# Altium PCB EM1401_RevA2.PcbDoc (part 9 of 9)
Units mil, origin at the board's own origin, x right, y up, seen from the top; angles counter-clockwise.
Board outline 7800 x 5300 mil, 6 copper layers (Top Layer, MidLayer1, MidLayer2, MidLayer3, MidLayer4, Bottom Layer), stack 16.8 mil thick; 751 components, 531 nets, 2554 pads, 1388 vias.
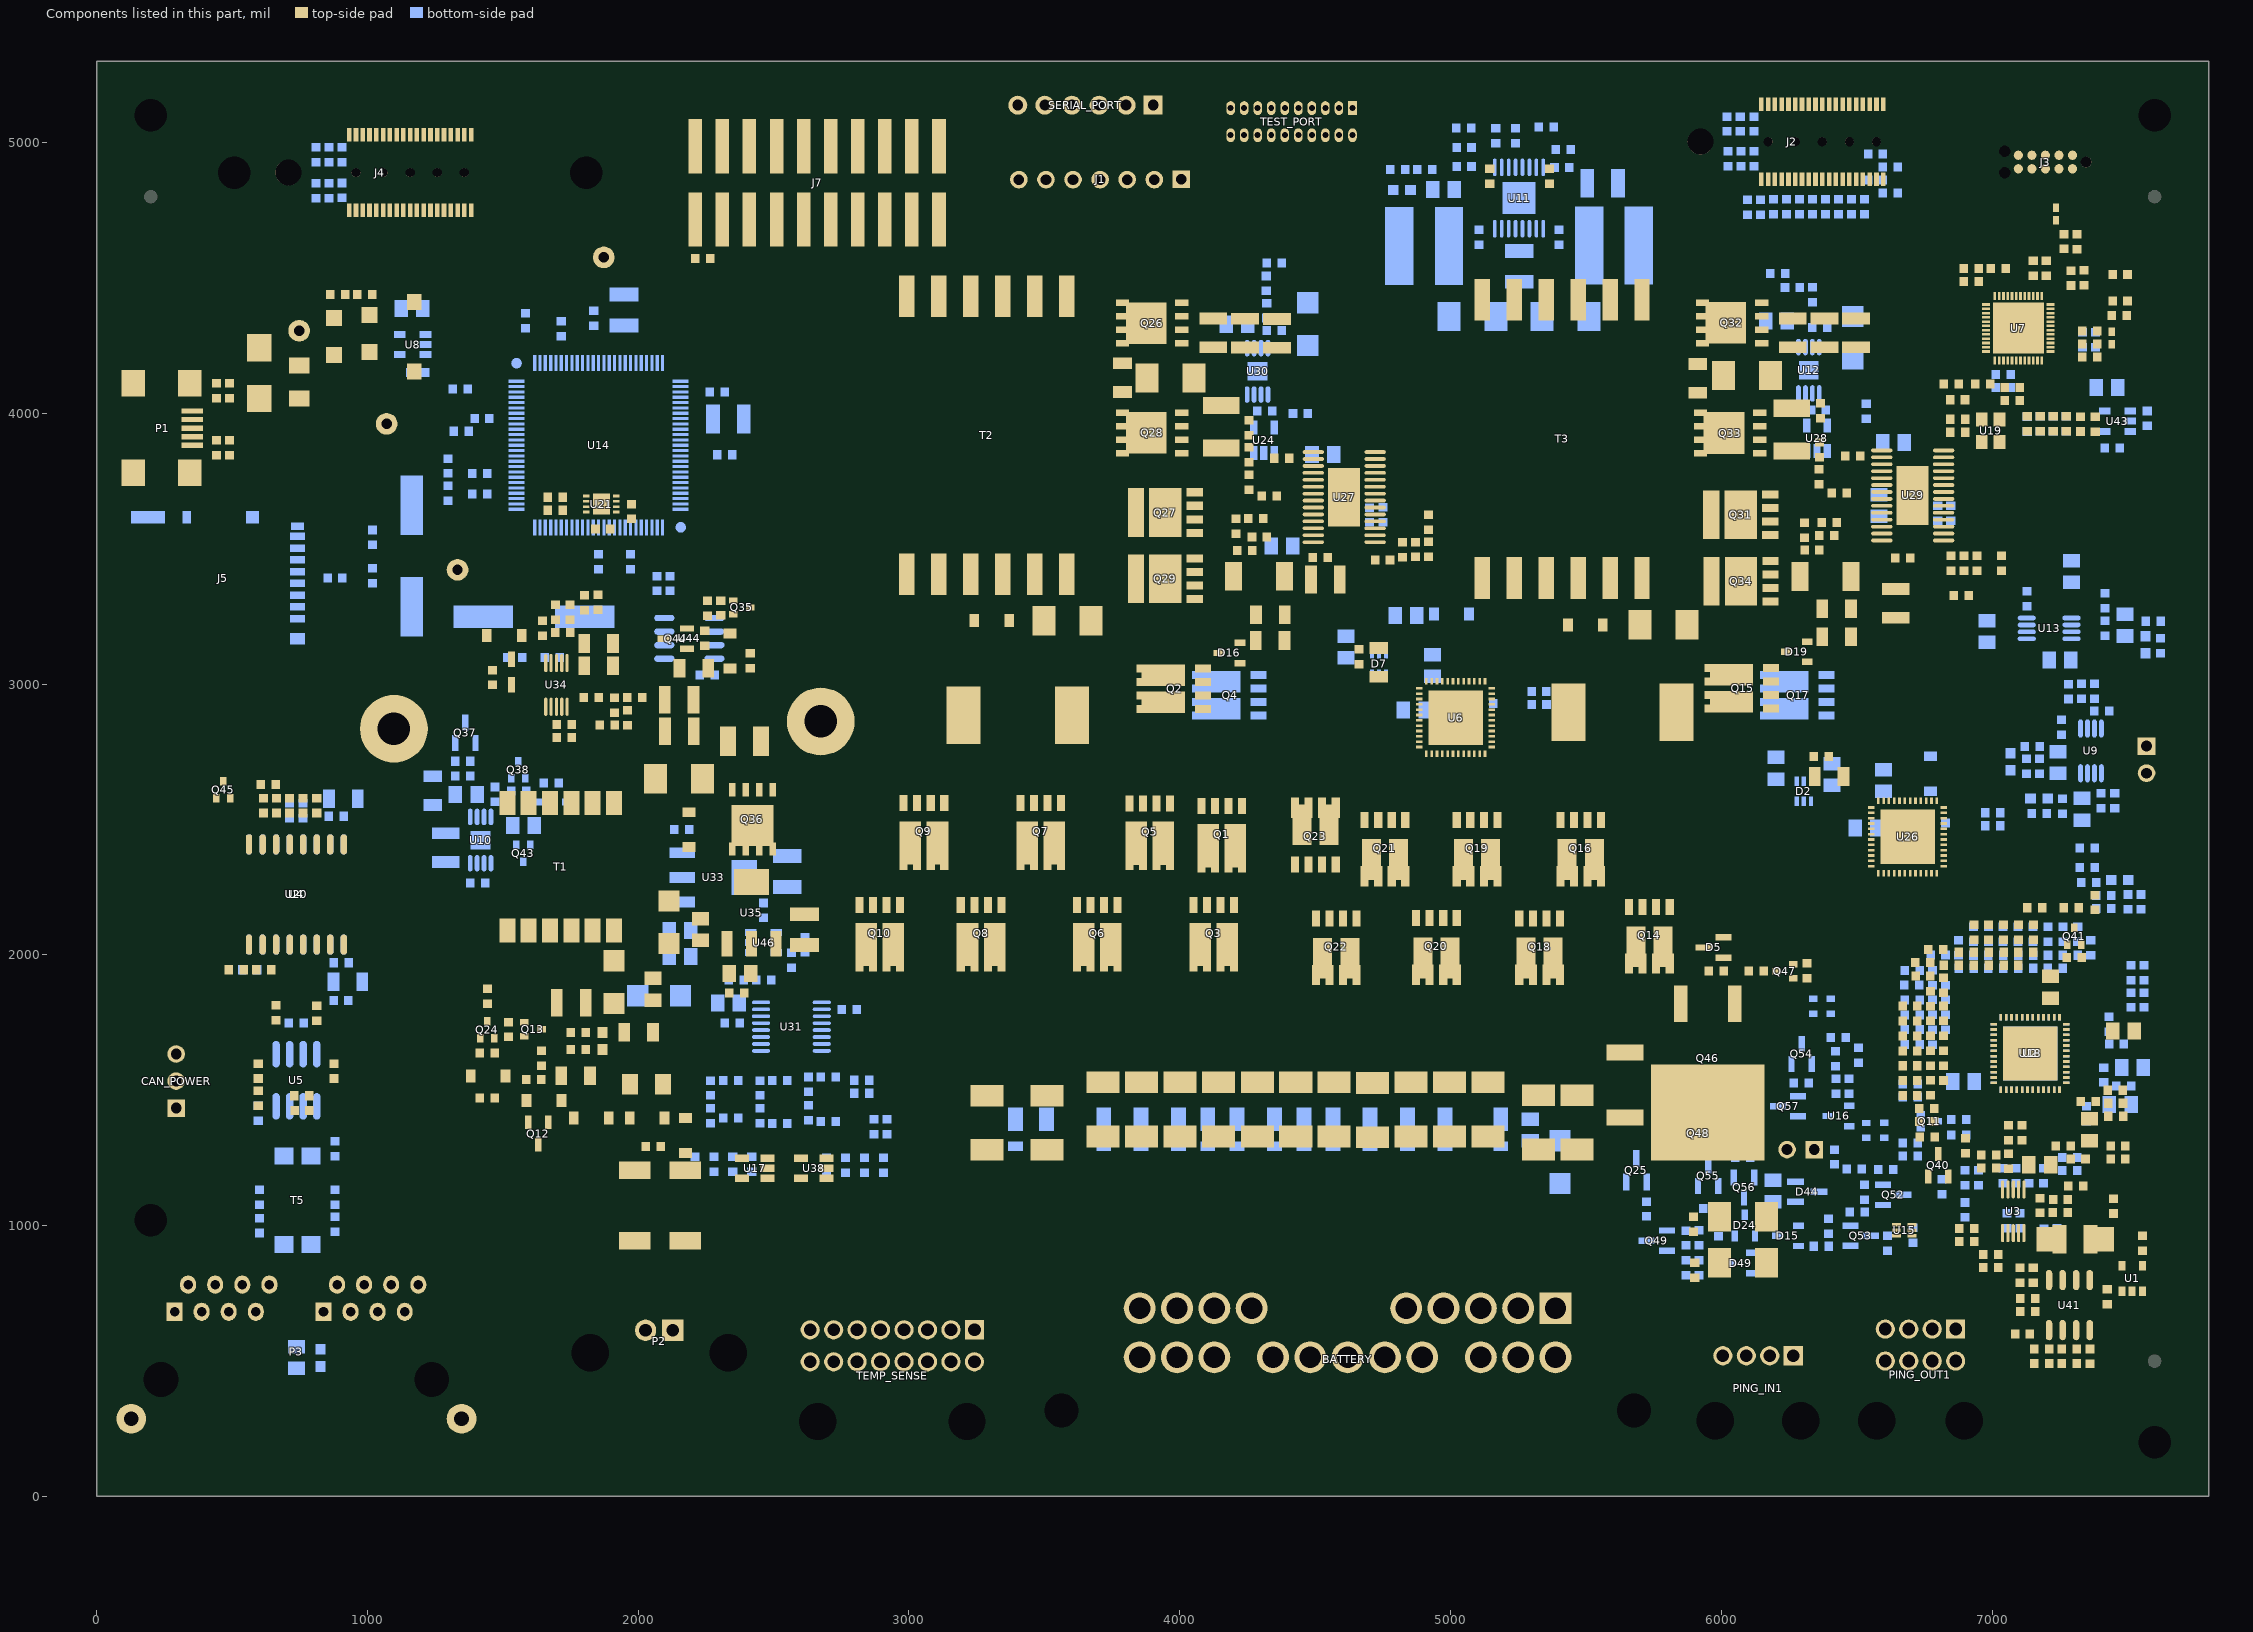
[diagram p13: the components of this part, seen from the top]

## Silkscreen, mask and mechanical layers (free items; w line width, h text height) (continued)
M12 Stackup:
  lines w15: 6208,7684.5 11163,7684.5 ; 6208,7953.7 11163,7953.7 ; 6148,5572 ccw(c6235,5572) 6235,5485 11136,5485 ccw(c11136,5572) 11223,5572 11223,8138 ccw(c11136,8138) 11136,8225 6235,8225 ccw(c6235,8138) 6148,8138 6148,5572
  text "Layer Stack Up Detail for: EM1401_RevA2.PcbDoc" at 6208,8014.45 h103
  text "Layer" at 6208,7853.2 h62
  text "Gerber" at 7976.19,7853.2 h62
  text "Copper" at 8902.98,7853.2 h62
  text "Dielectric" at 9931.01,7853.2 h62
  text "Name" at 6208,7729.2 h62
  text "Document" at 7976.19,7729.2 h62
  text "Thickness" at 8902.98,7729.2 h62
  text "Material" at 9931.01,7729.2 h62
  text "Top Solder Mask" at 6208,7552.5 h87
  text "(.GTS)" at 7976.19,7552.5 h87
  text "Solder Resist" at 9931.01,7552.5 h87
  text "Top Layer" at 6208,7303.5 h87
  text "(.GTL)" at 7976.19,7303.5 h87
  text "2.8mil" at 8902.98,7303.5 h87
  text "FR-4" at 9931.01,7179 h87
  text "MidLayer1" at 6208,7054.5 h87
  text "(.G1)" at 7976.19,7054.5 h87
  text "2.8mil" at 8902.98,7054.5 h87
  text "FR-4" at 9931.01,6930 h87
  text "MidLayer2" at 6208,6805.5 h87
  text "(.G2)" at 7976.19,6805.5 h87
  text "2.8mil" at 8902.98,6805.5 h87
  text "FR-4" at 9931.01,6681 h87
  text "MidLayer3" at 6208,6556.5 h87
  text "(.G3)" at 7976.19,6556.5 h87
  text "2.8mil" at 8902.98,6556.5 h87
  text "FR-4" at 9931.01,6432 h87
  text "MidLayer4" at 6208,6307.5 h87
  text "(.G4)" at 7976.19,6307.5 h87
  text "2.8mil" at 8902.98,6307.5 h87
  text "FR-4" at 9931.01,6183 h87
  text "Bottom Layer" at 6208,6058.5 h87
  text "(.GBL)" at 7976.19,6058.5 h87
  text "2.8mil" at 8902.98,6058.5 h87
  text "Bottom Solder Mask" at 6208,5809.5 h87
  text "(.GBS)" at 7976.19,5809.5 h87
  text "Solder Resist" at 9931.01,5809.5 h87
  text "Stack up to be specified by manufacturer for best fit for 62mil board" at 5923,5361 h80
  text ".Layer_Name" at 11494.5,1002.5 h80
M13 Component Bodies Top:
  text ".Layer_Name" at 11494.5,1002.5 h80
M14 Component Bodies Bottom:
  text ".Layer_Name" at 11494.5,1002.5 h80
M15 Courtyards Top:
  text ".Layer_Name" at 11494.5,1002.5 h80
M16 Courtyards Bottom:
  text ".Layer_Name" at 11494.5,1002.5 h80
Drill Drawing:
  text ".legend" at 7862,2261 h60
  text "Drill Table" at 7854,2148 h60
  text ".Layer_Name" at 11494.5,1002.5 h80

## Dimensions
421.63,2203 to 421.63,2265 on M2 Board Dimensions
1058.55,2255.92 to 430.63,2234 on M2 Board Dimensions
0,0 to 7800,0 on M2 Board Dimensions
0,0 to 0,5300 on M2 Board Dimensions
